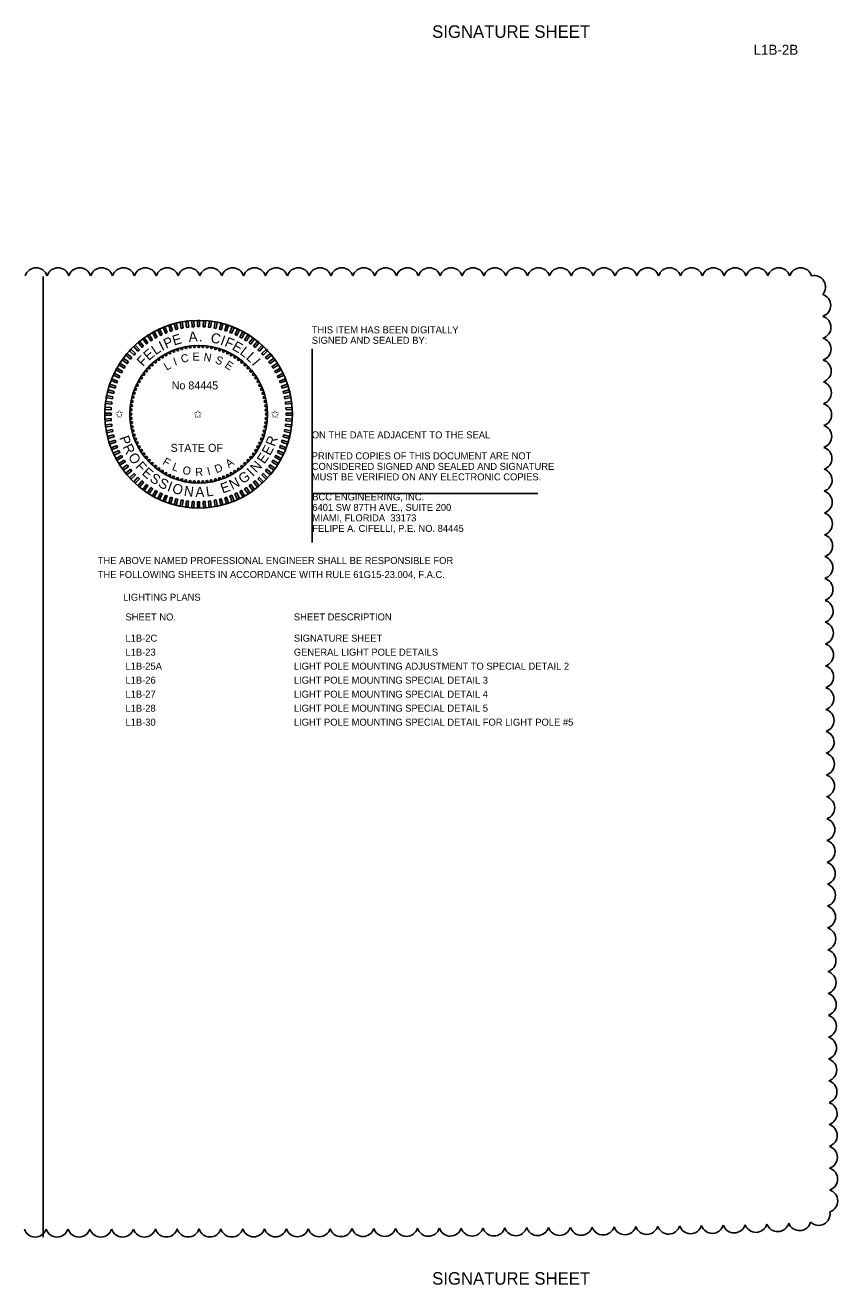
# Model space of a CAD drawing. Extents: x -811.2 to -755.6, y -2295.2 to -2235.1.
# Drawn here: x -803.27 to -795.14, y -2282.52 to -2269.93 of the extents above; entities that cross this region are included whole.
import ezdxf

# ---------------------------------------------------------------- set-up
doc = ezdxf.new("R2010")
doc.units = 0
for name, color, linetype in [('Cloud_dp', 7, 'Continuous'), ('Logo_dp', 7, 'Continuous'), ('NonPlottingEle_dp', 7, 'Continuous'), ('ScratchEle_dp', 7, 'Continuous'), ('SheetBorder_dp', 7, 'Continuous'), ('TextMisc', 7, 'Continuous'), ('TextNotes', 7, 'Continuous'), ('TextShtNo', 7, 'Continuous')]:
    doc.layers.add(name, color=color, linetype=linetype)

msp = doc.modelspace()

# ---------------------------------------------------------------- linework, layer by layer
at = {"layer": 'Cloud_dp'}
for centre, start, end in [((-803.157, -2272.472), 17.5, 162.5), ((-802.939, -2272.472), 17.5, 162.5), ((-802.721, -2272.472), 17.5, 162.5), ((-802.502, -2272.472), 17.5, 162.5), ((-802.284, -2272.472), 17.5, 162.5), ((-802.066, -2272.472), 17.5, 162.5), ((-801.847, -2272.472), 17.5, 162.5), ((-801.629, -2272.472), 17.5, 162.5), ((-801.411, -2272.472), 17.5, 162.5), ((-801.192, -2272.472), 17.5, 162.5), ((-800.974, -2272.472), 17.5, 162.5), ((-800.756, -2272.472), 17.5, 162.5), ((-800.537, -2272.472), 17.5, 162.5), ((-800.319, -2272.472), 17.5, 162.5), ((-800.101, -2272.472), 17.5, 162.5), ((-799.882, -2272.472), 17.5, 162.5), ((-799.664, -2272.472), 17.5, 162.5), ((-799.446, -2272.472), 17.5, 162.5), ((-799.227, -2272.472), 17.5, 162.5), ((-799.009, -2272.472), 17.5, 162.5), ((-798.791, -2272.472), 17.5, 162.5), ((-798.572, -2272.472), 17.5, 162.5), ((-798.354, -2272.472), 17.5, 162.5), ((-798.136, -2272.472), 17.5, 162.5), ((-797.917, -2272.472), 17.5, 162.5), ((-797.699, -2272.472), 17.5, 162.5), ((-797.481, -2272.472), 17.5, 162.5), ((-797.262, -2272.472), 17.5, 162.5), ((-797.044, -2272.472), 17.5, 162.5), ((-796.826, -2272.472), 17.5, 162.5), ((-796.607, -2272.472), 17.5, 162.5), ((-796.389, -2272.472), 17.5, 162.5), ((-796.171, -2272.472), 17.5, 162.5), ((-795.952, -2272.472), 17.5, 162.5), ((-795.734, -2272.472), 17.5, 162.5), ((-795.516, -2272.472), 17.5, 162.5), ((-795.381, -2272.549), 318.1116, 103.1116), ((-795.329, -2272.734), 287.9529, 72.9529), ((-795.327, -2272.953), 287.9529, 72.9529), ((-795.326, -2273.171), 287.9529, 72.9529), ((-795.324, -2273.389), 287.9529, 72.9529), ((-795.322, -2273.608), 287.9529, 72.9529), ((-795.32, -2273.826), 287.9529, 72.9529), ((-795.319, -2274.044), 287.9529, 72.9529), ((-795.317, -2274.263), 287.9529, 72.9529), ((-795.315, -2274.481), 287.9529, 72.9529), ((-795.314, -2274.699), 287.9529, 72.9529), ((-795.312, -2274.918), 287.9529, 72.9529), ((-795.31, -2275.136), 287.9529, 72.9529), ((-795.308, -2275.354), 287.9529, 72.9529), ((-795.307, -2275.573), 287.9529, 72.9529), ((-795.305, -2275.791), 287.9529, 72.9529), ((-795.303, -2276.009), 287.9529, 72.9529), ((-795.301, -2276.228), 287.9529, 72.9529), ((-795.3, -2276.446), 287.9529, 72.9529), ((-795.298, -2276.664), 287.9529, 72.9529), ((-795.296, -2276.882), 287.9529, 72.9529), ((-795.295, -2277.101), 287.9529, 72.9529), ((-795.293, -2277.319), 287.9527, 72.9527), ((-795.291, -2277.537), 287.9524, 72.9524), ((-795.289, -2277.756), 287.9521, 72.9521), ((-795.288, -2277.974), 287.9519, 72.9519), ((-795.286, -2278.192), 287.9515, 72.9515), ((-795.284, -2278.411), 287.9512, 72.9512), ((-795.282, -2278.629), 287.9508, 72.9508), ((-795.281, -2278.847), 287.9504, 72.9504), ((-795.279, -2279.066), 287.9499, 72.9499), ((-795.277, -2279.284), 287.9494, 72.9494), ((-795.276, -2279.502), 287.9488, 72.9488), ((-795.274, -2279.721), 287.9481, 72.9481), ((-795.272, -2279.939), 287.9473, 72.9473), ((-795.271, -2280.157), 287.9464, 72.9464), ((-795.269, -2280.376), 287.9452, 72.9452), ((-795.267, -2280.594), 287.9438, 72.9438), ((-795.265, -2280.812), 287.9419, 72.9419), ((-795.264, -2281.03), 287.9394, 72.9394), ((-795.262, -2281.249), 287.9355, 72.9355), ((-795.26, -2281.467), 287.9288, 72.9288), ((-795.259, -2281.685), 287.9106, 72.9106), ((-795.745, -2281.878), 199.5943, 344.5943), ((-795.527, -2281.868), 200.5167, 345.5167), ((-795.336, -2281.815), 225.4798, 10.4798), ((-803.166, -2281.932), 197.496, 342.496), ((-802.948, -2281.932), 197.5011, 342.5011), ((-802.729, -2281.932), 197.5111, 342.5111), ((-802.511, -2281.932), 197.522, 342.522), ((-802.293, -2281.932), 197.5335, 342.5335), ((-802.074, -2281.932), 197.5456, 342.5456), ((-801.856, -2281.931), 197.5582, 342.5582), ((-801.638, -2281.931), 197.5715, 342.5715), ((-801.42, -2281.931), 197.5855, 342.5855), ((-801.201, -2281.931), 197.6002, 342.6002), ((-800.983, -2281.93), 197.6157, 342.6157), ((-800.765, -2281.93), 197.6322, 342.6322), ((-800.546, -2281.929), 197.6497, 342.6497), ((-800.328, -2281.929), 197.6683, 342.6683), ((-800.11, -2281.928), 197.6881, 342.6881), ((-799.891, -2281.927), 197.7093, 342.7093), ((-799.673, -2281.926), 197.732, 342.732), ((-799.455, -2281.925), 197.7565, 342.7565), ((-799.236, -2281.924), 197.7829, 342.7829), ((-799.018, -2281.923), 197.8116, 342.8116), ((-798.8, -2281.922), 197.8429, 342.8429), ((-798.582, -2281.921), 197.8771, 342.8771), ((-798.363, -2281.919), 197.9149, 342.9149), ((-798.145, -2281.917), 197.9569, 342.9569), ((-797.927, -2281.916), 198.0039, 343.0039), ((-797.708, -2281.914), 198.0569, 343.0569), ((-797.49, -2281.911), 198.1174, 343.1174), ((-797.272, -2281.909), 198.1874, 343.1874), ((-797.054, -2281.906), 198.2696, 343.2696), ((-796.835, -2281.903), 198.368, 343.368), ((-796.617, -2281.899), 198.4888, 343.4888), ((-796.399, -2281.895), 198.642, 343.642), ((-796.181, -2281.891), 198.8454, 343.8454), ((-795.963, -2281.885), 199.1345, 344.1345)]:
    msp.add_arc(centre, 0.114, start, end, dxfattribs=at)
at = {"layer": 'Logo_dp'}
for p, q in [((-801.543, -2274.759), (-801.543, -2274.697)), ((-801.533, -2274.759), (-801.533, -2274.697)), ((-801.523, -2274.759), (-801.523, -2274.696))]:
    msp.add_line(p, q, dxfattribs=at)
for points in [[(-801.896, -2273.025), (-801.915, -2273.034), (-801.941, -2272.978), (-801.923, -2272.969)], [(-801.846, -2273.004), (-801.864, -2273.012), (-801.887, -2272.954), (-801.869, -2272.946)], [(-801.794, -2272.986), (-801.813, -2272.992), (-801.832, -2272.933), (-801.813, -2272.927)], [(-801.741, -2272.971), (-801.76, -2272.976), (-801.776, -2272.916), (-801.756, -2272.911)], [(-801.687, -2272.96), (-801.707, -2272.964), (-801.718, -2272.903), (-801.699, -2272.899)], [(-801.632, -2272.952), (-801.653, -2272.955), (-801.66, -2272.893), (-801.64, -2272.89)], [(-801.578, -2272.948), (-801.598, -2272.949), (-801.602, -2272.887), (-801.582, -2272.885)], [(-801.523, -2272.946), (-801.543, -2272.946), (-801.543, -2272.884), (-801.523, -2272.884)], [(-801.468, -2272.949), (-801.488, -2272.948), (-801.484, -2272.885), (-801.464, -2272.887)], [(-801.413, -2272.955), (-801.433, -2272.952), (-801.425, -2272.89), (-801.405, -2272.893)], [(-801.359, -2272.964), (-801.379, -2272.96), (-801.367, -2272.899), (-801.347, -2272.903)], [(-801.305, -2272.977), (-801.325, -2272.971), (-801.309, -2272.911), (-801.29, -2272.916)], [(-801.253, -2272.992), (-801.272, -2272.986), (-801.253, -2272.927), (-801.234, -2272.933)], [(-801.201, -2273.012), (-801.22, -2273.004), (-801.197, -2272.946), (-801.178, -2272.954)], [(-801.151, -2273.034), (-801.169, -2273.025), (-801.143, -2272.969), (-801.125, -2272.978)], [(-802.083, -2273.141), (-802.098, -2273.154), (-802.138, -2273.106), (-802.123, -2273.093)], [(-802.039, -2273.108), (-802.055, -2273.119), (-802.092, -2273.069), (-802.076, -2273.057)], [(-801.993, -2273.077), (-802.01, -2273.088), (-802.044, -2273.035), (-802.027, -2273.025)], [(-801.946, -2273.05), (-801.963, -2273.06), (-801.993, -2273.005), (-801.976, -2272.995)], [(-801.102, -2273.06), (-801.12, -2273.05), (-801.09, -2272.995), (-801.072, -2273.005)], [(-801.055, -2273.088), (-801.073, -2273.077), (-801.039, -2273.025), (-801.022, -2273.035)], [(-801.01, -2273.12), (-801.027, -2273.108), (-800.99, -2273.057), (-800.974, -2273.069)], [(-800.967, -2273.154), (-800.983, -2273.141), (-800.943, -2273.093), (-800.928, -2273.106)], [(-802.201, -2273.256), (-802.214, -2273.271), (-802.262, -2273.232), (-802.249, -2273.216)], [(-802.164, -2273.215), (-802.178, -2273.23), (-802.223, -2273.187), (-802.209, -2273.172)], [(-802.124, -2273.177), (-802.139, -2273.19), (-802.182, -2273.145), (-802.167, -2273.131)], [(-800.926, -2273.191), (-800.941, -2273.177), (-800.898, -2273.131), (-800.884, -2273.145)], [(-800.888, -2273.23), (-800.902, -2273.215), (-800.856, -2273.172), (-800.843, -2273.187)], [(-800.852, -2273.272), (-800.865, -2273.256), (-800.817, -2273.216), (-800.804, -2273.232)], [(-802.266, -2273.344), (-802.277, -2273.361), (-802.33, -2273.328), (-802.319, -2273.311)], [(-802.235, -2273.299), (-802.247, -2273.315), (-802.297, -2273.279), (-802.285, -2273.262)], [(-800.819, -2273.315), (-800.831, -2273.299), (-800.78, -2273.262), (-800.769, -2273.279)], [(-800.789, -2273.361), (-800.799, -2273.344), (-800.747, -2273.311), (-800.736, -2273.328)], [(-802.343, -2273.49), (-802.35, -2273.509), (-802.408, -2273.486), (-802.401, -2273.467)], [(-802.32, -2273.44), (-802.329, -2273.458), (-802.385, -2273.431), (-802.377, -2273.413)], [(-802.295, -2273.391), (-802.305, -2273.409), (-802.359, -2273.379), (-802.35, -2273.361)], [(-800.761, -2273.409), (-800.771, -2273.391), (-800.716, -2273.361), (-800.707, -2273.379)], [(-800.737, -2273.458), (-800.745, -2273.44), (-800.689, -2273.413), (-800.68, -2273.432)], [(-800.716, -2273.509), (-800.723, -2273.49), (-800.665, -2273.467), (-800.658, -2273.486)], [(-802.378, -2273.594), (-802.383, -2273.614), (-802.443, -2273.598), (-802.438, -2273.579)], [(-802.362, -2273.541), (-802.368, -2273.561), (-802.428, -2273.541), (-802.421, -2273.522)], [(-800.698, -2273.561), (-800.704, -2273.542), (-800.644, -2273.522), (-800.638, -2273.542)], [(-800.683, -2273.614), (-800.688, -2273.594), (-800.627, -2273.579), (-800.622, -2273.598)], [(-802.4, -2273.702), (-802.402, -2273.722), (-802.464, -2273.714), (-802.462, -2273.694)], [(-802.391, -2273.648), (-802.394, -2273.667), (-802.456, -2273.656), (-802.452, -2273.636)], [(-800.671, -2273.668), (-800.675, -2273.648), (-800.614, -2273.636), (-800.61, -2273.656)], [(-800.664, -2273.722), (-800.666, -2273.702), (-800.604, -2273.694), (-800.602, -2273.714)], [(-802.408, -2273.811), (-802.408, -2273.832), (-802.47, -2273.832), (-802.47, -2273.811)], [(-802.406, -2273.756), (-802.407, -2273.777), (-802.469, -2273.773), (-802.468, -2273.752)], [(-800.659, -2273.777), (-800.66, -2273.757), (-800.598, -2273.753), (-800.597, -2273.773)], [(-800.658, -2273.832), (-800.658, -2273.812), (-800.595, -2273.812), (-800.595, -2273.832)], [(-802.407, -2273.866), (-802.406, -2273.886), (-802.468, -2273.89), (-802.469, -2273.87)], [(-802.402, -2273.921), (-802.4, -2273.941), (-802.462, -2273.949), (-802.464, -2273.929)], [(-802.394, -2273.975), (-802.391, -2273.995), (-802.452, -2274.007), (-802.456, -2273.987)], [(-800.675, -2273.995), (-800.672, -2273.976), (-800.61, -2273.987), (-800.614, -2274.007)], [(-800.666, -2273.941), (-800.664, -2273.921), (-800.602, -2273.929), (-800.604, -2273.949)], [(-800.66, -2273.887), (-800.659, -2273.866), (-800.597, -2273.87), (-800.598, -2273.891)], [(-802.383, -2274.029), (-802.378, -2274.049), (-802.438, -2274.064), (-802.443, -2274.045)], [(-802.368, -2274.082), (-802.362, -2274.101), (-802.421, -2274.121), (-802.428, -2274.102)], [(-800.704, -2274.102), (-800.698, -2274.082), (-800.638, -2274.102), (-800.644, -2274.121)], [(-800.688, -2274.049), (-800.683, -2274.029), (-800.622, -2274.045), (-800.627, -2274.065)], [(-802.35, -2274.134), (-802.343, -2274.153), (-802.401, -2274.176), (-802.408, -2274.157)], [(-802.329, -2274.185), (-802.32, -2274.203), (-802.377, -2274.23), (-802.386, -2274.211)], [(-800.746, -2274.203), (-800.737, -2274.185), (-800.68, -2274.212), (-800.689, -2274.23)], [(-800.723, -2274.153), (-800.716, -2274.134), (-800.658, -2274.157), (-800.665, -2274.176)], [(-802.305, -2274.234), (-802.295, -2274.252), (-802.35, -2274.282), (-802.359, -2274.264)], [(-802.277, -2274.282), (-802.266, -2274.299), (-802.319, -2274.332), (-802.33, -2274.315)], [(-802.247, -2274.328), (-802.235, -2274.344), (-802.285, -2274.381), (-802.297, -2274.364)], [(-800.831, -2274.344), (-800.819, -2274.328), (-800.769, -2274.364), (-800.78, -2274.381)], [(-800.8, -2274.299), (-800.789, -2274.282), (-800.736, -2274.315), (-800.747, -2274.332)], [(-800.771, -2274.252), (-800.761, -2274.234), (-800.707, -2274.264), (-800.716, -2274.282)], [(-802.214, -2274.371), (-802.201, -2274.387), (-802.249, -2274.427), (-802.262, -2274.411)], [(-802.178, -2274.413), (-802.164, -2274.428), (-802.209, -2274.471), (-802.223, -2274.456)], [(-802.139, -2274.452), (-802.125, -2274.466), (-802.167, -2274.512), (-802.182, -2274.498)], [(-800.941, -2274.466), (-800.927, -2274.453), (-800.884, -2274.498), (-800.899, -2274.512)], [(-800.902, -2274.428), (-800.888, -2274.413), (-800.843, -2274.456), (-800.857, -2274.471)], [(-800.865, -2274.387), (-800.852, -2274.372), (-800.804, -2274.411), (-800.817, -2274.427)], [(-802.099, -2274.489), (-802.083, -2274.502), (-802.123, -2274.55), (-802.138, -2274.537)], [(-802.055, -2274.523), (-802.039, -2274.535), (-802.076, -2274.586), (-802.092, -2274.574)], [(-802.01, -2274.555), (-801.993, -2274.566), (-802.027, -2274.618), (-802.044, -2274.608)], [(-801.963, -2274.583), (-801.946, -2274.593), (-801.976, -2274.648), (-801.993, -2274.638)], [(-801.12, -2274.593), (-801.103, -2274.583), (-801.073, -2274.638), (-801.09, -2274.648)], [(-801.073, -2274.566), (-801.056, -2274.555), (-801.022, -2274.608), (-801.039, -2274.618)], [(-801.027, -2274.535), (-801.011, -2274.524), (-800.974, -2274.574), (-800.99, -2274.586)], [(-800.983, -2274.502), (-800.967, -2274.489), (-800.928, -2274.537), (-800.943, -2274.55)], [(-801.915, -2274.609), (-801.896, -2274.618), (-801.923, -2274.674), (-801.941, -2274.665)], [(-801.865, -2274.631), (-801.846, -2274.639), (-801.869, -2274.697), (-801.887, -2274.689)], [(-801.813, -2274.651), (-801.794, -2274.657), (-801.813, -2274.716), (-801.832, -2274.71)], [(-801.76, -2274.667), (-801.741, -2274.672), (-801.756, -2274.732), (-801.776, -2274.727)], [(-801.707, -2274.679), (-801.687, -2274.683), (-801.699, -2274.744), (-801.719, -2274.74)], [(-801.653, -2274.688), (-801.633, -2274.691), (-801.64, -2274.753), (-801.661, -2274.75)], [(-801.598, -2274.694), (-801.578, -2274.695), (-801.582, -2274.758), (-801.602, -2274.756)], [(-801.543, -2274.697), (-801.523, -2274.697), (-801.523, -2274.759), (-801.543, -2274.759)], [(-801.488, -2274.695), (-801.468, -2274.694), (-801.464, -2274.756), (-801.484, -2274.758)], [(-801.433, -2274.691), (-801.413, -2274.688), (-801.406, -2274.75), (-801.426, -2274.753)], [(-801.379, -2274.683), (-801.359, -2274.679), (-801.347, -2274.74), (-801.367, -2274.744)], [(-801.325, -2274.672), (-801.306, -2274.667), (-801.29, -2274.727), (-801.31, -2274.732)], [(-801.272, -2274.657), (-801.253, -2274.651), (-801.234, -2274.71), (-801.253, -2274.716)], [(-801.22, -2274.639), (-801.202, -2274.631), (-801.179, -2274.689), (-801.197, -2274.697)], [(-801.17, -2274.618), (-801.151, -2274.609), (-801.125, -2274.665), (-801.143, -2274.674)]]:
    msp.add_lwpolyline(points, close=True, dxfattribs=at)
for centre in [(-801.859, -2273.228), (-801.821, -2273.208), (-801.782, -2273.191), (-801.742, -2273.177), (-801.701, -2273.165), (-801.659, -2273.156), (-801.617, -2273.149), (-801.575, -2273.145), (-801.532, -2273.144), (-801.49, -2273.145), (-801.447, -2273.149), (-801.405, -2273.156), (-801.364, -2273.165), (-801.323, -2273.177), (-801.283, -2273.192), (-801.244, -2273.209), (-801.206, -2273.228), (-802.026, -2273.357), (-801.996, -2273.327), (-801.964, -2273.299), (-801.931, -2273.273), (-801.895, -2273.249), (-801.169, -2273.25), (-801.134, -2273.274), (-801.101, -2273.3), (-801.069, -2273.328), (-802.105, -2273.458), (-802.081, -2273.423), (-802.055, -2273.389), (-801.039, -2273.358), (-801.011, -2273.39), (-800.985, -2273.424), (-800.961, -2273.459), (-802.163, -2273.572), (-802.146, -2273.533), (-802.126, -2273.495), (-800.939, -2273.496), (-800.92, -2273.534), (-800.903, -2273.573), (-802.198, -2273.694), (-802.189, -2273.652), (-802.177, -2273.612), (-800.888, -2273.613), (-800.877, -2273.654), (-800.867, -2273.695), (-802.21, -2273.821), (-802.209, -2273.778), (-802.205, -2273.736), (-800.861, -2273.737), (-800.857, -2273.78), (-800.855, -2273.822), (-802.209, -2273.863), (-802.205, -2273.906), (-802.198, -2273.948), (-800.868, -2273.949), (-800.861, -2273.907), (-800.857, -2273.865), (-802.189, -2273.989), (-802.177, -2274.03), (-802.163, -2274.07), (-802.146, -2274.109), (-800.92, -2274.11), (-800.903, -2274.071), (-800.889, -2274.031), (-800.877, -2273.991), (-802.127, -2274.147), (-802.105, -2274.184), (-802.081, -2274.219), (-800.985, -2274.22), (-800.961, -2274.185), (-800.94, -2274.148), (-802.055, -2274.253), (-802.027, -2274.285), (-801.997, -2274.315), (-801.965, -2274.343), (-801.102, -2274.344), (-801.07, -2274.316), (-801.039, -2274.286), (-801.011, -2274.254), (-801.932, -2274.369), (-801.896, -2274.393), (-801.86, -2274.415), (-801.822, -2274.434), (-801.783, -2274.451), (-801.743, -2274.466), (-801.702, -2274.478), (-801.66, -2274.487), (-801.407, -2274.487), (-801.365, -2274.478), (-801.324, -2274.466), (-801.284, -2274.452), (-801.245, -2274.435), (-801.207, -2274.415), (-801.17, -2274.394), (-801.135, -2274.37), (-801.618, -2274.494), (-801.576, -2274.498), (-801.533, -2274.499), (-801.491, -2274.498), (-801.449, -2274.494)]:
    msp.add_circle(centre, 0.01, dxfattribs=at)
at = {"layer": 'NonPlottingEle_dp'}
for radius in [0.938, 0.688]:
    msp.add_circle((-801.533, -2273.822), radius, dxfattribs=at)
at = {"layer": 'ScratchEle_dp'}
for p, q in [((-800.397, -2273.168), (-800.397, -2275.103)), ((-800.397, -2274.613), (-798.141, -2274.613))]:
    msp.add_line(p, q, dxfattribs=at)
at = {"layer": 'SheetBorder_dp'}
msp.add_line((-803.086, -2282.046), (-803.086, -2272.446), dxfattribs=at)

# ---------------------------------------------------------------- texts
at = {"layer": 'Logo_dp'}
for s, height, rotation, p in [('I', 0.1, 26.8161, (-801.898, -2273.191)), ('P', 0.1, 23.2829, (-801.858, -2273.169)), ('E', 0.1, 16.5426, (-801.779, -2273.136)), ('A', 0.1, 4.421, (-801.63, -2273.099)), ('.', 0.1, 356.654, (-801.531, -2273.093)), ('C', 0.1, 347.7999, (-801.419, -2273.102)), ('I', 0.1, 340.0631, (-801.323, -2273.124)), ('F', 0.1, 336.5299, (-801.281, -2273.138)), ('E', 0.1, 330.0796, (-801.206, -2273.171)), ('E', 0.1, 40.1214, (-802.033, -2273.292)), ('L', 0.1, 33.0792, (-801.964, -2273.234)), ('C', 0.08, 12.2025, (-801.701, -2273.31)), ('E', 0.08, 0.4186, (-801.593, -2273.286)), ('N', 0.08, 349.2914, (-801.488, -2273.285)), ('L', 0.1, 323.0373, (-801.128, -2273.216)), ('L', 0.1, 316.7742, (-801.065, -2273.263)), ('F', 0.1, 46.5718, (-802.089, -2273.351)), ('L', 0.08, 30.4021, (-801.852, -2273.388)), ('I', 0.08, 20.0117, (-801.769, -2273.337)), ('S', 0.08, 337.0221, (-801.375, -2273.307)), ('E', 0.08, 325.8663, (-801.279, -2273.347)), ('I', 0.1, 310.5111, (-801.006, -2273.318)), ('P', 0.1, 289.4055, (-802.328, -2274.056)), ('R', 0.1, 69.5134, (-800.773, -2274.151)), ('R', 0.1, 296.1458, (-802.295, -2274.148)), ('O', 0.1, 303.9671, (-802.243, -2274.248)), ('E', 0.1, 55.4289, (-800.876, -2274.326)), ('E', 0.1, 62.4712, (-800.819, -2274.242)), ('F', 0.1, 312.628, (-802.171, -2274.35)), ('E', 0.1, 319.0783, (-802.107, -2274.419)), ('F', 0.08, 328.7241, (-801.901, -2274.318)), ('L', 0.08, 339.2916, (-801.804, -2274.377)), ('O', 0.08, 349.6821, (-801.699, -2274.417)), ('I', 0.08, 14.2037, (-801.437, -2274.432)), ('D', 0.08, 22.0128, (-801.355, -2274.413)), ('A', 0.08, 34.4992, (-801.231, -2274.361)), ('N', 0.1, 47.1788, (-800.955, -2274.415)), ('S', 0.1, 326.1206, (-802.03, -2274.485)), ('S', 0.1, 333.193, (-801.944, -2274.541)), ('R', 0.08, 2.3398, (-801.565, -2274.439)), ('N', 0.1, 26.8614, (-801.197, -2274.579)), ('G', 0.1, 35.1115, (-801.092, -2274.523)), ('I', 0.1, 43.6456, (-800.993, -2274.45)), ('I', 0.1, 340.2654, (-801.853, -2274.586)), ('O', 0.1, 343.7986, (-801.805, -2274.604)), ('N', 0.1, 352.4595, (-801.684, -2274.636)), ('A', 0.1, 0.7097, (-801.565, -2274.649)), ('L', 0.1, 8.4767, (-801.453, -2274.646)), ('E', 0.1, 19.8191, (-801.293, -2274.615))]:
    msp.add_text(s, height=height, rotation=rotation, dxfattribs=at).set_placement(p)
for s, p in [('No 84445', (-801.802, -2273.574)), ('✩', (-802.368, -2273.859)), ('✩', (-801.583, -2273.859)), ('✩', (-800.811, -2273.859)), ('STATE OF', (-801.813, -2274.198))]:
    msp.add_text(s, height=0.08, dxfattribs=at).set_placement(p)
at = {"layer": 'TextMisc'}
for s, height, p in [('       SIGNATURE SHEET         ', 0.125, (-799.524, -2270.06)), ('THIS ITEM HAS BEEN DIGITALLY', 0.07, (-800.402, -2273.013)), ('SIGNED AND SEALED BY:', 0.07, (-800.402, -2273.118)), ('ON THE DATE ADJACENT TO THE SEAL', 0.07, (-800.402, -2274.063)), ('PRINTED COPIES OF THIS DOCUMENT ARE NOT ', 0.07, (-800.402, -2274.273)), ('CONSIDERED SIGNED AND SEALED AND SIGNATURE ', 0.07, (-800.402, -2274.378)), ('MUST BE VERIFIED ON ANY ELECTRONIC COPIES.', 0.07, (-800.402, -2274.483)), ('6401 SW 87TH AVE., SUITE 200', 0.07, (-800.397, -2274.788)), ('BCC ENGINEERING, INC.', 0.07, (-800.397, -2274.683)), ('MIAMI, FLORIDA  33173', 0.07, (-800.397, -2274.893)), ('FELIPE A. CIFELLI, P.E. NO. 84445', 0.07, (-800.397, -2274.998)), ('THE ABOVE NAMED PROFESSIONAL ENGINEER SHALL BE RESPONSIBLE FOR ', 0.07, (-802.541, -2275.319)), ('THE FOLLOWING SHEETS IN ACCORDANCE WITH RULE 61G15-23.004, F.A.C.', 0.07, (-802.541, -2275.459)), ('LIGHTING PLANS', 0.07, (-802.288, -2275.686)), ('       SIGNATURE SHEET         ', 0.125, (-799.524, -2282.522))]:
    msp.add_text(s, height=height, dxfattribs=at).set_placement(p)
at = {"layer": 'TextNotes'}
for s, p in [('SHEET NO.', (-802.264, -2275.883)), ('SHEET DESCRIPTION', (-800.581, -2275.883)), ('L1B-2C', (-802.264, -2276.095)), ('SIGNATURE SHEET', (-800.581, -2276.095)), ('L1B-23', (-802.264, -2276.235)), ('GENERAL LIGHT POLE DETAILS', (-800.581, -2276.235)), ('L1B-25A', (-802.264, -2276.375)), ('LIGHT POLE MOUNTING ADJUSTMENT TO SPECIAL DETAIL 2', (-800.581, -2276.375)), ('L1B-26', (-802.264, -2276.515)), ('LIGHT POLE MOUNTING SPECIAL DETAIL 3', (-800.581, -2276.515)), ('L1B-27', (-802.264, -2276.655)), ('LIGHT POLE MOUNTING SPECIAL DETAIL 4', (-800.581, -2276.655)), ('L1B-28', (-802.264, -2276.795)), ('LIGHT POLE MOUNTING SPECIAL DETAIL 5', (-800.581, -2276.795)), ('L1B-30', (-802.264, -2276.935)), ('LIGHT POLE MOUNTING SPECIAL DETAIL FOR LIGHT POLE #5', (-800.581, -2276.935))]:
    msp.add_text(s, height=0.07, dxfattribs=at).set_placement(p)
at = {"layer": 'TextShtNo'}
msp.add_text('L1B-2B ', height=0.1, dxfattribs=at).set_placement((-795.986, -2270.229))

doc.saveas('drawing.dxf')
